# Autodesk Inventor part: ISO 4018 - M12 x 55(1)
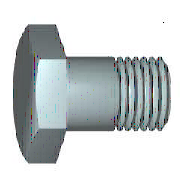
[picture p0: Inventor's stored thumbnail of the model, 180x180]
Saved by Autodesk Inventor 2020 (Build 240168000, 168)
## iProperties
Created: 2019-01
Part Number: ISO 4018 - M12 x 55(1)
Material: Ocel
Description: Šrouby se šestihrannou hlavou se závitem k hlavě. Výrobní třída C
Document SubType Name: Modeling
Standard: ISO 4018
Designer: doma
Standard Revision: Fourth edition 2011-04-01
Standards Organization: ISO
Language: cs-CZ
Size Designation: M12 x 55
Categories: <MemberInstance><Categories><Category DisplayName="Spojovací materiál" InternalName="e4da775c-781d-43d5-af7c-5136215cf5a6" Mnemonic="FSTN"><Category DisplayName
Density: 7.85 g/cm^3
Appearance: Plech
IsCustomPart: 0
Author: doma
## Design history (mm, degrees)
node "WorkPlane1"
node "WorkPoint1"
node "MSC_A1"
node "MSC_PF1"
node "MSC_PT1"
body "Solid1"
node "Náčrt1"
sketch "Náčrt2"
  geometry: L1 (-9, 5.196)-(-9, -5.196); L2 (0, 10.392)-(-9, 5.196); L3 (9, 5.196)-(0, 10.392); L4 (9, -5.196)-(9, 5.196); L5 (0, -10.392)-(9, -5.196); L6 (-9, -5.196)-(0, -10.392); C1 r 9 at (0, 0); 1 further point
  constraints: 12 end point, 6 tangent, 2 parallel, 2 vertical, 1 centre point
  dimensions: "d1" = 18 diameter of C1 (= ParS); "d29" = 0 distance of point (0, 0) C1.centre; "d30" = 0 distance of C1.centre point (0, 0)
extrude "Vysunutí1" new body sketch "Náčrt2" distance "d6" = 7.5 (= ParK); taper "d7" = 0 deg
revolve "Rotace1" stored, may be unused: angle "d14" = 360 deg
revolve "Rotace2" stored, may be unused: angle "d21" = 360 deg
chamfer "Zkosení1" distance "d22" = 0.875 (= 0.5 x PTC); stored, may be unused: second distance "d23" = 0.875 (= 0.5 x PTC), angle "d39" = 45 deg
fillet "Zaoblení1" dims "d24" = 0.6 (= r)
feature "Závit1" dims "d32" = 0, "b" = 51.5 (= NLG - 2 x PTC)
sketch "Náčrt3"
  geometry: L1 (9, 7.5)-(10.492, 7.5); L2 (10.492, 6.639)-(9, 7.5); L3 (10.492, 7.5)-(10.492, 6.639); L4 (0, -1.5)-(0, 9) reference; L5 (10.392, 0)-(10.392, 7.5) reference
  constraints: 6 end point, 1 horizontal, 1 vertical
  dimensions: "d25" = 0.1 distance between parallel lines of L5 L3; "d26" = 0 distance from line of L5.end L1; "d27" = 60 deg angle of L3 L2; "d28" = 9 distance from line of L4 L1.start (= 0.5 x ParS)
sketch "Náčrt4"
  geometry: L1 (0, -55)-(0, 0); L2 (-6, -55)-(0, -55); L3 (-6, 0)-(-6, -55); L4 (0, 0)-(-6, 0); L5 (0, -55)-(0, 0); L6 (-7.2, 0)-(1.2, 0) reference; L7 (0, -66)-(0, 11) reference
  constraints: 10 end point, 2 horizontal, 2 vertical
  dimensions: "d18" = 6 distance of L1.start L2.start (= 0.5 x NND); "d20" = 55 distance of L3.start L2.start (= NLG); "d33" = 0 distance between parallel lines of L7 L1; "d34" = 0 distance between parallel lines of L6 L4
other parameters: "NND" = 12 [user parameter; used in 2 equation terms], "NLG" = 55 [user parameter; used in 2 equation terms], "PTC" = 1.75 [user parameter; used in 3 equation terms], "ParK" = 7.5 [user parameter; used in 1 equation term], "ParS" = 18 [user parameter; used in 3 equation terms], "msp_es" = 10.39261 (= 0.577367 x ParS) [user parameter], "r" = 0.6 [user parameter; used in 1 equation term], "d2" = 15 (derived), "d4" = 17.32102 (derived), "d8" = 15 (derived), "d10" = 0 (derived), "d12" = 30 deg (derived), "d15" = 0 (derived), "d37" = 0, "d38" = 0, "d40" = 0, "d41" = 0, "d42" = 0, "THREADDIA" = 12 (= NND) [user parameter]
